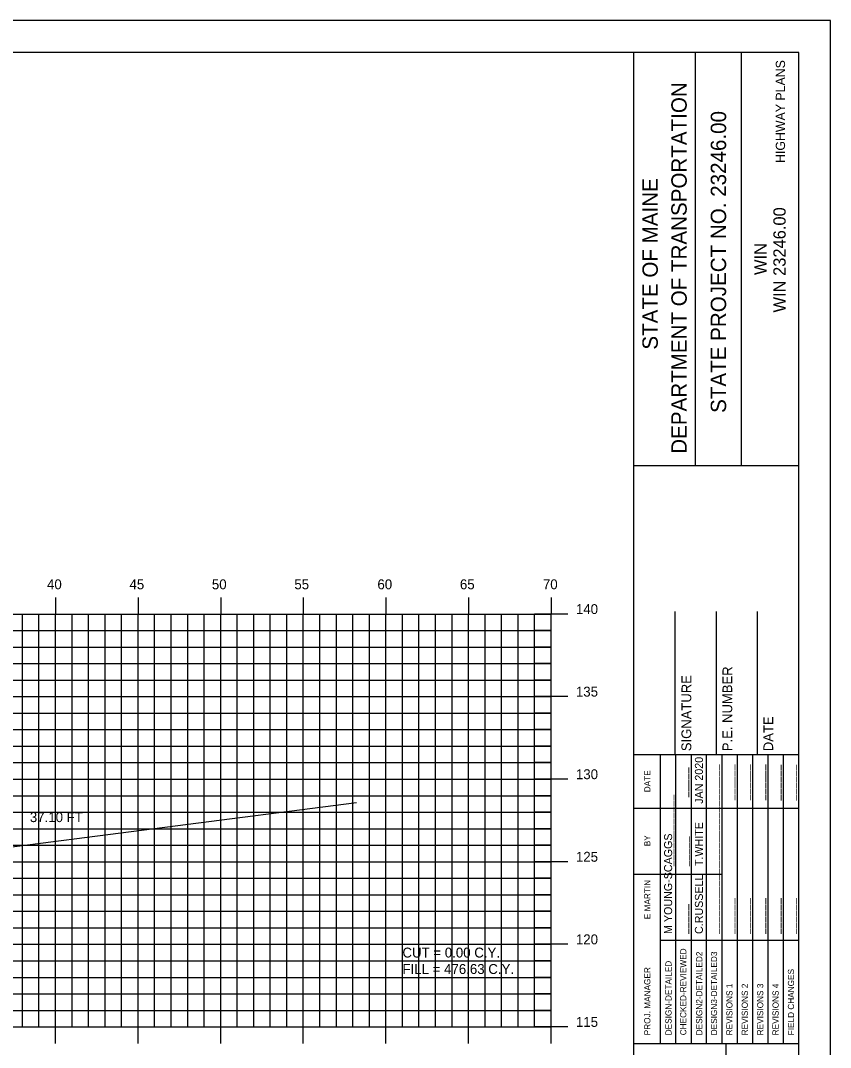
# Model space of a CAD drawing. Extents: x 1146081 to 1146251, y 608981 to 609091.
# Drawn here: x 1146202 to 1146251.1, y 609029.1 to 609091.3 of the extents above; entities that cross this region are included whole.
import ezdxf

# ---------------------------------------------------------------- set-up
doc = ezdxf.new("R2010")
doc.units = 0
for name, color, linetype in [('BORDER', 7, 'Continuous'), ('D_Text_Standard', 7, 'Continuous'), ('H_V ANNOTATION', 7, 'Continuous'), ('HIGHWAY_TITLE', 7, 'Continuous'), ('MAJOR', 7, 'Continuous'), ('MINOR', 7, 'Continuous'), ('PLOT BOUNDARY', 7, 'Continuous'), ('S_Roadway_Centerline', 7, 'Continuous')]:
    doc.layers.add(name, color=color, linetype=linetype)

msp = doc.modelspace()

# ---------------------------------------------------------------- linework, layer by layer
at = {"layer": 'BORDER'}
for p, q in [((1146239.158, 608984.335), (1146239.158, 609089.335)), ((1146242.887, 609064.332), (1146242.887, 609089.332)), ((1146245.682, 609064.332), (1146245.682, 609089.332)), ((1146239.159, 609064.329), (1146249.158, 609064.329)), ((1146241.658, 609046.838), (1146241.658, 609055.485)), ((1146244.158, 609046.838), (1146244.158, 609055.485)), ((1146246.658, 609046.838), (1146246.658, 609055.485)), ((1146239.158, 609046.838), (1146249.158, 609046.838)), ((1146239.158, 609029.338), (1146249.158, 609029.338)), ((1146244.749, 608994.338), (1146244.749, 609029.338))]:
    msp.add_line(p, q, dxfattribs=at)
msp.add_lwpolyline([(1146089.158, 608984.335), (1146249.158, 608984.335), (1146249.158, 609089.335), (1146089.158, 609089.335)], close=True, dxfattribs=at)
for points in [[(1146240.773, 609043.588), (1146240.773, 609046.838)], [(1146241.706, 609029.341), (1146241.706, 609046.838)], [(1146242.638, 609046.838), (1146242.638, 609029.341)], [(1146243.569, 609029.341), (1146243.569, 609046.838)], [(1146244.501, 609029.341), (1146244.501, 609046.838)], [(1146245.433, 609029.341), (1146245.433, 609046.838)], [(1146246.364, 609029.341), (1146246.364, 609046.838)], [(1146247.296, 609029.341), (1146247.296, 609046.838)], [(1146248.228, 609029.341), (1146248.228, 609046.838)], [(1146240.774, 609029.341), (1146240.774, 609046.132)], [(1146239.158, 609043.588), (1146249.158, 609043.588)], [(1146239.158, 609039.588), (1146240.774, 609039.588)], [(1146240.773, 609039.588), (1146244.5, 609039.588)], [(1146240.773, 609035.588), (1146249.158, 609035.588)]]:
    msp.add_lwpolyline(points, dxfattribs=at)
at = {"layer": 'MAJOR'}
for p, q in [((1146204.158, 609056.337), (1146204.158, 609055.335)), ((1146209.158, 609056.337), (1146209.158, 609055.335)), ((1146214.158, 609056.337), (1146214.158, 609055.335)), ((1146219.158, 609056.337), (1146219.158, 609055.335)), ((1146224.158, 609056.337), (1146224.158, 609055.335)), ((1146229.158, 609056.337), (1146229.158, 609055.335)), ((1146234.158, 609056.337), (1146234.158, 609055.335)), ((1146094.158, 609055.335), (1146234.158, 609055.335)), ((1146094.158, 609055.335), (1146234.158, 609055.335)), ((1146204.158, 609030.335), (1146204.158, 609055.335)), ((1146209.158, 609030.335), (1146209.158, 609055.335)), ((1146214.158, 609030.335), (1146214.158, 609055.335)), ((1146219.158, 609030.335), (1146219.158, 609055.335)), ((1146224.158, 609030.335), (1146224.158, 609055.335)), ((1146229.158, 609030.335), (1146229.158, 609055.335)), ((1146235.16, 609055.335), (1146233.156, 609055.335)), ((1146234.158, 609030.335), (1146234.158, 609055.335)), ((1146234.158, 609030.335), (1146234.158, 609055.335)), ((1146094.158, 609050.335), (1146234.158, 609050.335)), ((1146235.16, 609050.335), (1146233.156, 609050.335)), ((1146094.158, 609045.335), (1146234.158, 609045.335)), ((1146235.16, 609045.335), (1146233.156, 609045.335)), ((1146094.158, 609040.335), (1146234.158, 609040.335)), ((1146235.16, 609040.335), (1146233.156, 609040.335)), ((1146094.158, 609035.335), (1146234.158, 609035.335)), ((1146235.16, 609035.335), (1146233.156, 609035.335)), ((1146094.158, 609030.335), (1146234.158, 609030.335)), ((1146094.158, 609030.335), (1146234.158, 609030.335)), ((1146204.158, 609029.333), (1146204.158, 609030.335)), ((1146209.158, 609029.333), (1146209.158, 609030.335)), ((1146214.158, 609029.333), (1146214.158, 609030.335)), ((1146219.158, 609029.333), (1146219.158, 609030.335)), ((1146224.158, 609029.333), (1146224.158, 609030.335)), ((1146229.158, 609029.333), (1146229.158, 609030.335)), ((1146235.16, 609030.335), (1146233.156, 609030.335)), ((1146234.158, 609029.333), (1146234.158, 609030.335))]:
    msp.add_line(p, q, dxfattribs=at)
at = {"layer": 'MINOR'}
for p, q in [((1146202.158, 609030.335), (1146202.158, 609055.335)), ((1146203.158, 609030.335), (1146203.158, 609055.335)), ((1146205.158, 609030.335), (1146205.158, 609055.335)), ((1146206.158, 609030.335), (1146206.158, 609055.335)), ((1146207.158, 609030.335), (1146207.158, 609055.335)), ((1146208.158, 609030.335), (1146208.158, 609055.335)), ((1146210.158, 609030.335), (1146210.158, 609055.335)), ((1146211.158, 609030.335), (1146211.158, 609055.335)), ((1146212.158, 609030.335), (1146212.158, 609055.335)), ((1146213.158, 609030.335), (1146213.158, 609055.335)), ((1146215.158, 609030.335), (1146215.158, 609055.335)), ((1146216.158, 609030.335), (1146216.158, 609055.335)), ((1146217.158, 609030.335), (1146217.158, 609055.335)), ((1146218.158, 609030.335), (1146218.158, 609055.335)), ((1146220.158, 609030.335), (1146220.158, 609055.335)), ((1146221.158, 609030.335), (1146221.158, 609055.335)), ((1146222.158, 609030.335), (1146222.158, 609055.335)), ((1146223.158, 609030.335), (1146223.158, 609055.335)), ((1146225.158, 609030.335), (1146225.158, 609055.335)), ((1146226.158, 609030.335), (1146226.158, 609055.335)), ((1146227.158, 609030.335), (1146227.158, 609055.335)), ((1146228.158, 609030.335), (1146228.158, 609055.335)), ((1146230.158, 609030.335), (1146230.158, 609055.335)), ((1146231.158, 609030.335), (1146231.158, 609055.335)), ((1146232.158, 609030.335), (1146232.158, 609055.335)), ((1146233.158, 609030.335), (1146233.158, 609055.335)), ((1146094.158, 609054.335), (1146234.158, 609054.335)), ((1146234.158, 609054.335), (1146233.156, 609054.335)), ((1146094.158, 609053.335), (1146234.158, 609053.335)), ((1146234.158, 609053.335), (1146233.156, 609053.335)), ((1146094.158, 609052.335), (1146234.158, 609052.335)), ((1146234.158, 609052.335), (1146233.156, 609052.335)), ((1146094.158, 609051.335), (1146234.158, 609051.335)), ((1146234.158, 609051.335), (1146233.156, 609051.335)), ((1146094.158, 609049.335), (1146234.158, 609049.335)), ((1146234.158, 609049.335), (1146233.156, 609049.335)), ((1146094.158, 609048.335), (1146234.158, 609048.335)), ((1146234.158, 609048.335), (1146233.156, 609048.335)), ((1146094.158, 609047.335), (1146234.158, 609047.335)), ((1146234.158, 609047.335), (1146233.156, 609047.335)), ((1146094.158, 609046.335), (1146234.158, 609046.335)), ((1146234.158, 609046.335), (1146233.156, 609046.335)), ((1146094.158, 609044.335), (1146234.158, 609044.335)), ((1146234.158, 609044.335), (1146233.156, 609044.335)), ((1146094.158, 609043.335), (1146234.158, 609043.335)), ((1146234.158, 609043.335), (1146233.156, 609043.335)), ((1146094.158, 609042.335), (1146234.158, 609042.335)), ((1146234.158, 609042.335), (1146233.156, 609042.335)), ((1146094.158, 609041.335), (1146234.158, 609041.335)), ((1146234.158, 609041.335), (1146233.156, 609041.335)), ((1146094.158, 609039.335), (1146234.158, 609039.335)), ((1146234.158, 609039.335), (1146233.156, 609039.335)), ((1146094.158, 609038.335), (1146234.158, 609038.335)), ((1146234.158, 609038.335), (1146233.156, 609038.335)), ((1146094.158, 609037.335), (1146234.158, 609037.335)), ((1146234.158, 609037.335), (1146233.156, 609037.335)), ((1146094.158, 609036.335), (1146234.158, 609036.335)), ((1146234.158, 609036.335), (1146233.156, 609036.335)), ((1146094.158, 609034.335), (1146234.158, 609034.335)), ((1146234.158, 609034.335), (1146233.156, 609034.335)), ((1146094.158, 609033.335), (1146234.158, 609033.335)), ((1146234.158, 609033.335), (1146233.156, 609033.335)), ((1146094.158, 609032.335), (1146234.158, 609032.335)), ((1146234.158, 609032.335), (1146233.156, 609032.335)), ((1146094.158, 609031.335), (1146234.158, 609031.335)), ((1146234.158, 609031.335), (1146233.156, 609031.335))]:
    msp.add_line(p, q, dxfattribs=at)
at = {"layer": 'PLOT BOUNDARY'}
msp.add_lwpolyline([(1146081.065, 608981.276), (1146251.065, 608981.276), (1146251.065, 609091.276), (1146081.065, 609091.276)], close=True, dxfattribs=at)
at = {"layer": 'S_Roadway_Centerline'}
msp.add_lwpolyline([(1146109.994, 609036.218), (1146127.386, 609037.487), (1146129.573, 609037.653), (1146130.865, 609037.83), (1146136.476, 609038.551), (1146145.16, 609040.869), (1146146.117, 609041.121), (1146149.881, 609041.769), (1146150.681, 609041.862), (1146159.752, 609042.222), (1146161.743, 609042.288), (1146170.756, 609042.071), (1146172.573, 609042.017), (1146176.099, 609041.605), (1146176.621, 609041.535), (1146178.817, 609040.219), (1146184.994, 609036.462), (1146186.117, 609036.191), (1146189.498, 609037.815), (1146190.601, 609039.556), (1146199.152, 609040.937), (1146222.375, 609043.92)], dxfattribs=at)

# ---------------------------------------------------------------- texts
at = {"layer": 'BORDER'}
for s, height, p in [('DEPARTMENT OF TRANSPORTATION', 0.93176, (1146242.365, 609065.041)), ('STATE PROJECT NO. 23246.00', 0.93176, (1146244.75, 609067.517)), ('STATE OF MAINE', 0.93176, (1146240.614, 609071.347)), ('WIN 23246.00', 0.74527, (1146248.354, 609073.596)), ('WIN', 0.7453, (1146247.195, 609075.865)), ('P.E. NUMBER', 0.59055, (1146245.119, 609047.03)), ('SIGNATURE', 0.5906, (1146242.639, 609047.03)), ('DATE', 0.5906, (1146247.599, 609047.03)), ('JAN 2020', 0.4845, (1146243.345, 609043.843)), ('DATE', 0.3714, (1146240.163, 609044.544)), ('_____', 0.4845, (1146242.376, 609044.243)), ('______', 0.4845, (1146244.239, 609044.063)), ('______', 0.4845, (1146245.171, 609044.065)), ('______', 0.4845, (1146246.102, 609044.067)), ('______', 0.4845, (1146247.034, 609044.067)), ('______', 0.4845, (1146247.966, 609044.036)), ('______', 0.4845, (1146248.897, 609044.036)), ('____________', 0.48455, (1146241.481, 609040.073)), ('____________', 0.48455, (1146244.239, 609040.073)), ('T.WHITE', 0.4845, (1146243.345, 609040.073)), ('BY', 0.3714, (1146240.163, 609041.273)), ('M YOUNG-SCAGGS', 0.48455, (1146241.481, 609035.961)), ('_____', 0.4845, (1146242.413, 609040.073)), ('____________', 0.48455, (1146244.239, 609035.961)), ('E MARTIN', 0.3727, (1146240.163, 609036.855)), ('C.RUSSELL', 0.4845, (1146243.345, 609035.961)), ('_____', 0.4845, (1146242.376, 609035.961)), ('______', 0.4845, (1146245.171, 609035.961)), ('______', 0.4845, (1146246.102, 609035.961)), ('______', 0.4845, (1146247.034, 609035.961)), ('______', 0.4845, (1146247.966, 609035.961)), ('______', 0.4845, (1146248.897, 609035.961)), ('CHECKED-REVIEWED', 0.37275, (1146242.339, 609029.826)), ('DESIGN2-DETAILED2', 0.37275, (1146243.308, 609029.826)), ('DESIGN3-DETAILED3', 0.37275, (1146244.203, 609029.826)), ('DESIGN-DETAILED', 0.37275, (1146241.445, 609029.826)), ('PROJ. MANAGER', 0.37275, (1146240.163, 609029.826)), ('FIELD CHANGES', 0.37275, (1146248.861, 609029.826)), ('REVISIONS 1', 0.37275, (1146245.134, 609029.826)), ('REVISIONS 2', 0.37275, (1146246.066, 609029.826)), ('REVISIONS 3', 0.37275, (1146246.998, 609029.826)), ('REVISIONS 4', 0.37275, (1146247.929, 609029.826))]:
    msp.add_text(s, height=height, rotation=90, dxfattribs=at).set_placement(p)
at = {"layer": 'D_Text_Standard'}
for s, p in [('37.10 FT', (1146202.605, 609042.735)), ('CUT = 0.00 C.Y.', (1146225.158, 609034.535)), ('FILL = 476.63 C.Y.', (1146225.158, 609033.539))]:
    msp.add_text(s, height=0.6, dxfattribs=at).set_placement(p)
at = {"layer": 'H_V ANNOTATION'}
for s, p in [('40', (1146203.644, 609056.835)), ('45', (1146208.636, 609056.835)), ('50', (1146213.623, 609056.835)), ('55', (1146218.615, 609056.835)), ('60', (1146223.644, 609056.835)), ('65', (1146228.636, 609056.835)), ('70', (1146233.66, 609056.835)), ('140', (1146235.658, 609055.335)), ('135', (1146235.658, 609050.335)), ('130', (1146235.658, 609045.335)), ('125', (1146235.658, 609040.335)), ('120', (1146235.658, 609035.335)), ('115', (1146235.658, 609030.335))]:
    msp.add_text(s, height=0.6, dxfattribs=at).set_placement(p)
at = {"layer": 'HIGHWAY_TITLE'}
msp.add_text('HIGHWAY PLANS', height=0.55901, rotation=90, dxfattribs=at).set_placement((1146248.317, 609082.65))

doc.saveas('drawing.dxf')
